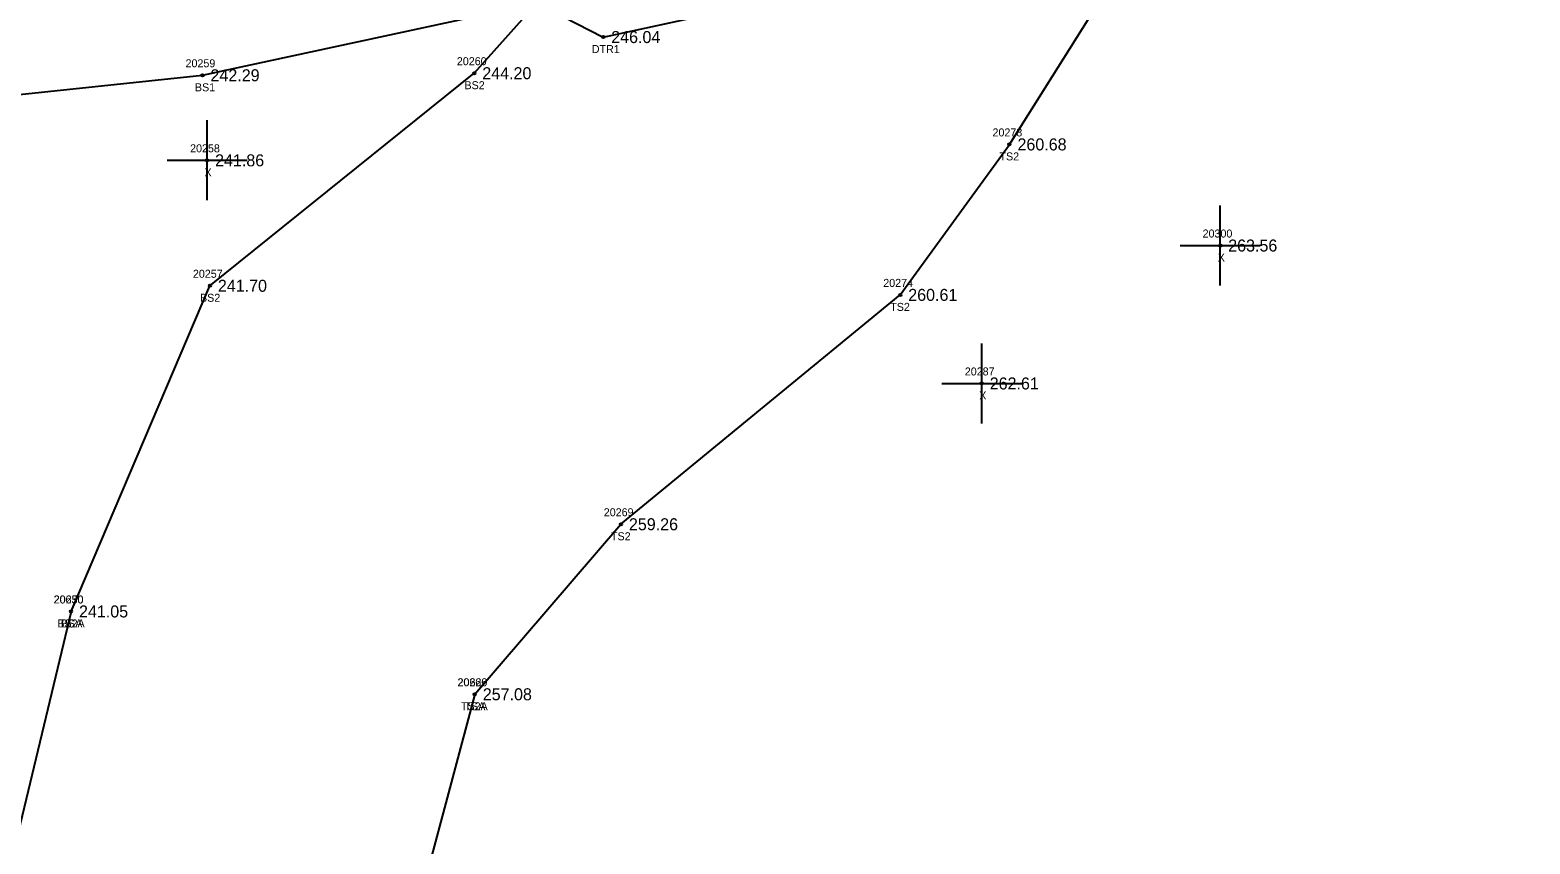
# Model space of a CAD drawing. Extents: x 2275563 to 2277161, y 1075719 to 1076412.
# Drawn here: x 2276514 to 2276701.4, y 1075959.9 to 1076061.7 of the extents above; entities that cross this region are included whole.
import ezdxf

# ---------------------------------------------------------------- set-up
doc = ezdxf.new("R2010")
doc.units = 0
for name, color, linetype in [('RD_DTM_BkLn2', 7, 'Continuous'), ('RD_DTM_BkLn_txCode', 7, 'Continuous'), ('RD_EX_H2O', 7, 'Continuous'), ('RD_EX_H2O_txCode', 7, 'Continuous'), ('RD_EX_Misc', 7, 'Continuous'), ('RD_EX_Misc_txCode', 7, 'Continuous'), ('RD_EX_TX_H2O_ELEV', 7, 'Continuous'), ('RD_EX_TX_Misc_ELEV', 7, 'Continuous'), ('RD_SMD_Locator', 7, 'Continuous')]:
    doc.layers.add(name, color=color, linetype=linetype)

msp = doc.modelspace()

# ---------------------------------------------------------------- linework, layer by layer
at = {"layer": 'RD_DTM_BkLn2'}
for points in [[(2276569.56, 1075978.62), (2276587.82, 1075999.87), (2276622.72, 1076028.54), (2276636.37, 1076047.35), (2276661.39, 1076087.16)], [(2276373.09, 1076038.49), (2276389.65, 1076038.07), (2276402.95, 1076045.94), (2276434.46, 1076042.78), (2276488.57, 1076051.06), (2276535.54, 1076055.99), (2276577.32, 1076064.99)], [(2276519.11, 1075988.97), (2276536.46, 1076029.68), (2276569.5, 1076056.25), (2276577.32, 1076064.99)], [(2276519.11, 1075988.97), (2276497.82, 1075900.18), (2276501, 1075833.77), (2276548.94, 1075764.25)], [(2276569.56, 1075978.62), (2276539.85, 1075867.33), (2276562.4, 1075835.97)]]:
    msp.add_lwpolyline(points, dxfattribs=at)
at = {"layer": 'RD_EX_H2O'}
msp.add_lwpolyline([(2276577.32, 1076064.99), (2276585.61, 1076060.77), (2276608.72, 1076065.79), (2276630.67, 1076076.21), (2276642.12, 1076079.44), (2276661.39, 1076087.16), (2276674.74, 1076089.6), (2276720.85, 1076101.92), (2276769.56, 1076115.83), (2276815.16, 1076127.06), (2276862.66, 1076139.65), (2276909.53, 1076154.75), (2276961.42, 1076172.61), (2277010.89, 1076191.18), (2277066.25, 1076211.87), (2277143.49, 1076241.1)], dxfattribs=at)
at = {"layer": 'RD_EX_Misc'}
for p, q in [((2276536.11, 1076040.36), (2276536.11, 1076050.36)), ((2276531.11, 1076045.36), (2276541.11, 1076045.36)), ((2276662.7, 1076029.71), (2276662.7, 1076039.71)), ((2276657.7, 1076034.71), (2276667.7, 1076034.71)), ((2276632.9, 1076012.47), (2276632.9, 1076022.47)), ((2276627.9, 1076017.47), (2276637.9, 1076017.47))]:
    msp.add_line(p, q, dxfattribs=at)
at = {"layer": 'RD_SMD_Locator'}
for centre in [(2276585.61, 1076060.77), (2276535.54, 1076055.99), (2276569.5, 1076056.25), (2276636.37, 1076047.35), (2276536.11, 1076045.36), (2276662.7, 1076034.71), (2276536.46, 1076029.68), (2276622.72, 1076028.54), (2276632.9, 1076017.47), (2276587.82, 1075999.87), (2276519.11, 1075988.97), (2276519.11, 1075988.97), (2276569.56, 1075978.62), (2276569.56, 1075978.62)]:
    msp.add_circle(centre, 0.15, dxfattribs=at)

# ---------------------------------------------------------------- texts
at = {"layer": 'RD_DTM_BkLn_txCode'}
for s, p in [('20259', (2276533.42, 1076056.99)), ('20260', (2276567.32, 1076057.25)), ('BS1', (2276534.59, 1076053.99)), ('BS2', (2276568.27, 1076054.25)), ('20278', (2276634.25, 1076048.35)), ('TS2', (2276635.12, 1076045.35)), ('20257', (2276534.34, 1076030.68)), ('20274', (2276620.6, 1076029.54)), ('BS2', (2276535.23, 1076027.68)), ('TS2', (2276621.47, 1076026.54)), ('20269', (2276585.68, 1076000.87)), ('TS2', (2276586.58, 1075997.87)), ('20630', (2276516.93, 1075989.97)), ('20250', (2276516.96, 1075989.97)), ('BS2A', (2276517.4, 1075986.97)), ('BSA', (2276517.85, 1075986.97)), ('20266', (2276567.39, 1075979.62)), ('20629', (2276567.42, 1075979.62)), ('TS2A', (2276567.83, 1075976.62)), ('TSA', (2276568.28, 1075976.62))]:
    msp.add_text(s, height=1, dxfattribs=at).set_placement(p)
at = {"layer": 'RD_EX_H2O_txCode'}
msp.add_text('DTR1', height=1, dxfattribs=at).set_placement((2276584.18, 1076058.77))
at = {"layer": 'RD_EX_Misc_txCode'}
for s, p in [('20258', (2276533.99, 1076046.36)), ('X', (2276535.79, 1076043.36)), ('20300', (2276660.5, 1076035.71)), ('X', (2276662.39, 1076032.71)), ('20287', (2276630.79, 1076018.47)), ('X', (2276632.59, 1076015.47))]:
    msp.add_text(s, height=1, dxfattribs=at).set_placement(p)
at = {"layer": 'RD_EX_TX_H2O_ELEV'}
msp.add_text('246.04', height=1.5, dxfattribs=at).set_placement((2276586.61, 1076060.02))
at = {"layer": 'RD_EX_TX_Misc_ELEV'}
for s, p in [('242.29', (2276536.54, 1076055.24)), ('244.20', (2276570.5, 1076055.5)), ('260.68', (2276637.37, 1076046.6)), ('241.86', (2276537.11, 1076044.61)), ('263.56', (2276663.7, 1076033.96)), ('241.70', (2276537.46, 1076028.93)), ('260.61', (2276623.72, 1076027.79)), ('262.61', (2276633.9, 1076016.72)), ('259.26', (2276588.82, 1075999.12)), ('241.05', (2276520.11, 1075988.22)), ('241.05', (2276520.11, 1075988.22)), ('257.08', (2276570.56, 1075977.87)), ('257.08', (2276570.56, 1075977.87))]:
    msp.add_text(s, height=1.5, dxfattribs=at).set_placement(p)

doc.saveas('drawing.dxf')
